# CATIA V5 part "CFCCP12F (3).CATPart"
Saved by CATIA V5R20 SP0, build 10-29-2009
Part number: CFCCP12F (3)
Revision: TUTTO
Definition: NON CONOSCIUTO
Nomenclature: CFCCP12F (3)
Source: Unknown
Bounding box of the stored display mesh (mm): x -60 to 60, y -39 to 39, z 0 to 10.5
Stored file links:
  C:\Users\Utente\Desktop\IO LAVORO\3D X SITO CF\X 3D SITO CF 27-09-2020\CFCCP\CFCCP12F\CFCCP12F (3).CATPart
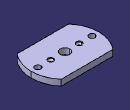
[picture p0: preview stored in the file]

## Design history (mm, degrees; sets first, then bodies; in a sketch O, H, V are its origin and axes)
Body1 "Foro Ø5.5 (5.5)-1" (main body)
  Solid1: solid without history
